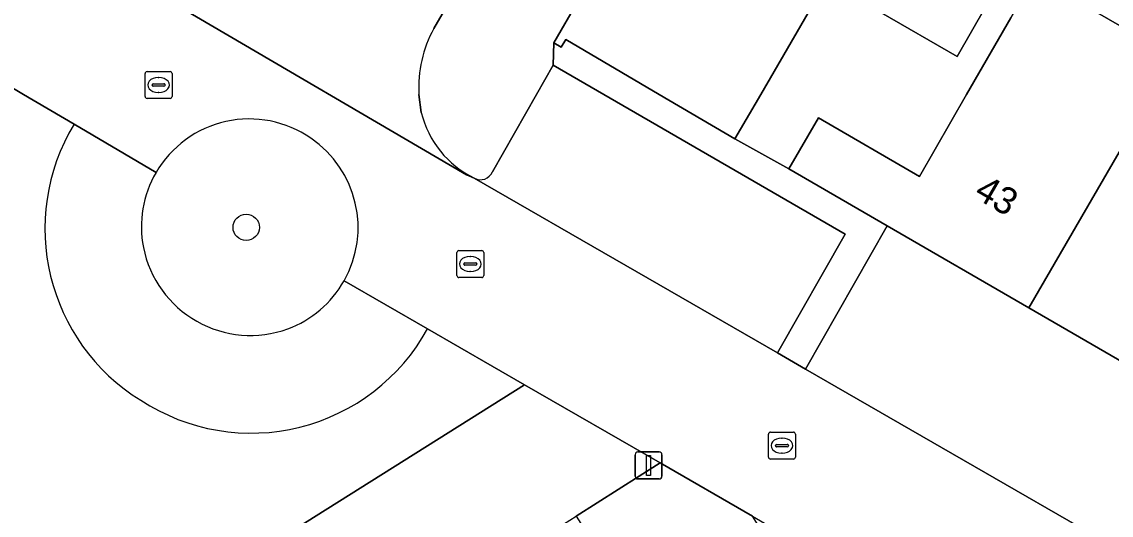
# Model space of a CAD drawing. Extents: x 160023 to 161302, y 384750 to 385707.
# Drawn here: x 160282.85 to 160323.26, y 384984.38 to 385002.69 of the extents above; entities that cross this region are included whole.
import ezdxf

# ---------------------------------------------------------------- set-up
doc = ezdxf.new("R2010")
doc.units = 0
for name, color, linetype in [('IMGEO_Boom', 7, 'Continuous'), ('IMGEO_Erf', 7, 'Continuous'), ('IMGEO_Groenvoorziening', 7, 'Continuous'), ('IMGEO_Haag', 7, 'Continuous'), ('IMGEO_Kolk', 7, 'Continuous'), ('IMGEO_Lichtmast', 7, 'Continuous'), ('IMGEO_Muur', 7, 'Continuous'), ('IMGEO_Pand', 7, 'Continuous'), ('IMGEO_Pand_nummerreeks', 7, 'Continuous'), ('IMGEO_Parkeervlak_open', 7, 'Continuous'), ('IMGEO_Rijbaan_lokaal_open', 7, 'Continuous'), ('IMGEO_Voetpad_open', 7, 'Continuous')]:
    doc.layers.add(name, color=color, linetype=linetype)

msp = doc.modelspace()

# ---------------------------------------------------------------- linework, layer by layer
at = {"layer": 'IMGEO_Boom'}
msp.add_circle((160291.176, 384995.065), 0.489, dxfattribs=at)
at = {"layer": 'IMGEO_Erf'}
for points in [[(160326.462, 385035.188), (160321.307, 385038.162), (160317.354, 385031.285), (160319.024, 385030.345), (160319.56, 385031.262), (160323.014, 385029.244), (160321.908, 385027.343), (160318.446, 385029.357), (160316.226, 385025.503), (160322.8, 385021.689), (160319.391, 385015.793), (160316.031, 385009.982), (160312.732, 385004.276), (160310.26, 385000), (160309.303, 384998.344), (160311.305, 384997.238), (160312.398, 384999.124), (160316.144, 384996.952), (160317.891, 385000), (160319.528, 385002.843), (160321.089, 385005.554), (160323.428, 385004.207), (160322.747, 385003.026), (160325.604, 385001.381)], [(160325.137, 384989.216), (160320.202, 384992.078), (160314.945, 384995.127), (160311.924, 384989.805), (160329.09, 384979.915)]]:
    msp.add_lwpolyline(points, dxfattribs=at)
msp.add_lwpolyline([(160318.609, 385003.264), (160317.539, 385001.409), (160314.716, 385003.036), (160315.785, 385004.891)], close=True, dxfattribs=at)
at = {"layer": 'IMGEO_Groenvoorziening'}
msp.add_lwpolyline([(160303.418, 384984.353), (160306.764, 384979.072), (160311.42, 384982.022), (160309.954, 384984.347), (160306.528, 384986.323)], close=True, dxfattribs=at)
for centre, radius, start, end in [((160291.291, 384995.085), 4.002, 55.2003, 149.7961), ((160291.316, 384995.056), 4.011, 330.4848, 55.7305), ((160291.288, 384995.084), 4, 149.7696, 191.0385), ((160291.338, 384995.11), 4.054, 191.2672, 289.865), ((160291.315, 384995.057), 4.012, 290.4291, 330.4795)]:
    msp.add_arc(centre, radius, start, end, dxfattribs=at)
at = {"layer": 'IMGEO_Haag'}
msp.add_lwpolyline([(160303.418, 384984.353), (160306.764, 384979.072), (160311.42, 384982.022), (160309.954, 384984.347), (160306.528, 384986.323)], close=True, dxfattribs=at)
at = {"layer": 'IMGEO_Kolk'}
for p, q in [((160287.426, 384999.92), (160287.426, 385000.772)), ((160287.501, 385000.846), (160288.353, 385000.846)), ((160287.914, 385000.626), (160287.939, 385000.626)), ((160288.427, 385000.772), (160288.427, 384999.92)), ((160287.685, 385000.34), (160287.685, 385000.352)), ((160288.123, 385000.303), (160287.725, 385000.303)), ((160287.728, 385000.389), (160288.126, 385000.389)), ((160288.169, 385000.352), (160288.169, 385000.34)), ((160288.353, 384999.846), (160287.501, 384999.846)), ((160287.937, 385000.066), (160287.912, 385000.066)), ((160298.988, 384993.278), (160298.988, 384994.13)), ((160299.063, 384994.204), (160299.915, 384994.204)), ((160299.989, 384994.13), (160299.989, 384993.278)), ((160299.247, 384993.698), (160299.247, 384993.71)), ((160299.29, 384993.747), (160299.688, 384993.747)), ((160299.476, 384993.984), (160299.501, 384993.984)), ((160299.731, 384993.71), (160299.731, 384993.698)), ((160299.685, 384993.661), (160299.287, 384993.661)), ((160299.499, 384993.424), (160299.474, 384993.424)), ((160299.915, 384993.204), (160299.063, 384993.204)), ((160310.544, 384986.54), (160310.544, 384987.392)), ((160310.619, 384987.466), (160311.471, 384987.466)), ((160311.032, 384987.246), (160311.057, 384987.246)), ((160311.545, 384987.392), (160311.545, 384986.54)), ((160310.803, 384986.96), (160310.803, 384986.972)), ((160311.241, 384986.923), (160310.843, 384986.923)), ((160310.846, 384987.009), (160311.244, 384987.009)), ((160311.287, 384986.972), (160311.287, 384986.96)), ((160311.471, 384986.466), (160310.619, 384986.466)), ((160311.055, 384986.686), (160311.03, 384986.686))]:
    msp.add_line(p, q, dxfattribs=at)
for points in [[(160287.426, 384999.92), (160287.426, 385000.772)], [(160287.501, 385000.846), (160288.353, 385000.846)], [(160288.427, 385000.772), (160288.427, 384999.92)], [(160288.353, 384999.846), (160287.501, 384999.846)], [(160298.988, 384993.278), (160298.988, 384994.13)], [(160299.063, 384994.204), (160299.915, 384994.204)], [(160299.989, 384994.13), (160299.989, 384993.278)], [(160299.915, 384993.204), (160299.063, 384993.204)], [(160310.544, 384986.54), (160310.544, 384987.392)], [(160310.619, 384987.466), (160311.471, 384987.466)], [(160311.545, 384987.392), (160311.545, 384986.54)], [(160311.471, 384986.466), (160310.619, 384986.466)]]:
    msp.add_lwpolyline(points, dxfattribs=at)
for centre, radius, start, end in [((160287.503, 385000.77), 0.0765, 91.552, 178.448), ((160287.503, 385000.77), 0.0765, 91.552, 178.448), ((160288.351, 385000.77), 0.0765, 1.552, 88.448), ((160288.351, 385000.77), 0.0765, 1.552, 88.448), ((160287.725, 385000.349), 0.0403, 85.8775, 175.7526), ((160287.722, 385000.339), 0.0366, 178.938, 274.7102), ((160288.126, 385000.346), 0.043, 264.8664, 352.4533), ((160288.13, 385000.351), 0.0386, 1.7309, 96.639), ((160287.503, 384999.922), 0.0765, 181.552, 268.448), ((160287.503, 384999.922), 0.0765, 181.552, 268.448), ((160288.351, 384999.922), 0.0765, 271.552, 358.448), ((160288.351, 384999.922), 0.0765, 271.552, 358.448), ((160299.065, 384994.128), 0.0765, 91.552, 178.448), ((160299.065, 384994.128), 0.0765, 91.552, 178.448), ((160299.913, 384994.128), 0.0765, 1.552, 88.448), ((160299.913, 384994.128), 0.0765, 1.552, 88.448), ((160299.287, 384993.707), 0.0403, 85.8775, 175.7526), ((160299.284, 384993.697), 0.0366, 178.938, 274.7102), ((160299.688, 384993.704), 0.043, 264.8664, 352.4533), ((160299.692, 384993.709), 0.0386, 1.7309, 96.639), ((160299.065, 384993.28), 0.0765, 181.552, 268.448), ((160299.065, 384993.28), 0.0765, 181.552, 268.448), ((160299.913, 384993.28), 0.0765, 271.552, 358.448), ((160299.913, 384993.28), 0.0765, 271.552, 358.448), ((160310.621, 384987.39), 0.0765, 91.552, 178.448), ((160310.621, 384987.39), 0.0765, 91.552, 178.448), ((160311.469, 384987.39), 0.0765, 1.552, 88.448), ((160311.469, 384987.39), 0.0765, 1.552, 88.448), ((160310.843, 384986.969), 0.0403, 85.8775, 175.7526), ((160310.84, 384986.959), 0.0366, 178.938, 274.7102), ((160311.244, 384986.966), 0.043, 264.8664, 352.4533), ((160311.248, 384986.971), 0.0386, 1.7309, 96.639), ((160310.621, 384986.542), 0.0765, 181.552, 268.448), ((160310.621, 384986.542), 0.0765, 181.552, 268.448), ((160311.469, 384986.542), 0.0765, 271.552, 358.448), ((160311.469, 384986.542), 0.0765, 271.552, 358.448)]:
    msp.add_arc(centre, radius, start, end, dxfattribs=at)
for centre, major_axis, ratio, start_param, end_param in [((160287.913, 385000.346), (-0.387, 0.002), 0.722429, 4.712389, 7.853982), ((160287.938, 385000.346), (-0.39, 0.002), 0.717154, 1.570796, 4.712389), ((160299.475, 384993.704), (-0.387, 0.002), 0.722429, 4.712389, 7.853982), ((160299.5, 384993.704), (-0.39, 0.002), 0.717154, 1.570796, 4.712389), ((160311.031, 384986.966), (-0.387, 0.002), 0.722429, 4.712389, 7.853982), ((160311.056, 384986.966), (-0.39, 0.002), 0.717154, 1.570796, 4.712389)]:
    msp.add_ellipse(centre, major_axis=major_axis, ratio=ratio, start_param=start_param, end_param=end_param, dxfattribs=at)
at = {"layer": 'IMGEO_Lichtmast'}
for p, q in [((160305.603, 384985.83), (160305.603, 384986.63)), ((160305.603, 384986.63), (160305.603, 384985.83)), ((160305.703, 384986.73), (160306.493, 384986.73)), ((160306.493, 384986.73), (160305.703, 384986.73)), ((160306.593, 384986.63), (160306.593, 384985.83)), ((160306.593, 384985.83), (160306.593, 384986.63)), ((160306.493, 384985.73), (160305.703, 384985.73)), ((160305.703, 384985.73), (160306.493, 384985.73))]:
    msp.add_line(p, q, dxfattribs=at)
msp.add_lwpolyline([(160306.023, 384986.605), (160306.173, 384986.605), (160306.173, 384985.855), (160306.023, 384985.855), (160306.023, 384986.605)], dxfattribs=at)
for centre, start, end in [((160305.703, 384986.63), 90, 180), ((160305.703, 384986.63), 90, 180), ((160306.493, 384986.63), 0, 90), ((160306.493, 384986.63), 360, 90), ((160305.703, 384985.83), 180, 270), ((160305.703, 384985.83), 180, 270), ((160306.493, 384985.83), 270, 0), ((160306.493, 384985.83), 270, 0)]:
    msp.add_arc(centre, 0.1, start, end, dxfattribs=at)
at = {"layer": 'IMGEO_Muur'}
msp.add_lwpolyline([(160309.303, 384998.344), (160311.305, 384997.238)], dxfattribs=at)
at = {"layer": 'IMGEO_Pand'}
for points in [[(160302.587, 385001.917), (160302.863, 385001.754), (160303.031, 385002.04), (160306.493, 385000), (160309.303, 384998.344), (160310.26, 385000), (160312.732, 385004.276), (160306.193, 385008.153)], [(160324.717, 384999.853), (160325.604, 385001.381), (160322.747, 385003.026), (160323.428, 385004.207), (160321.089, 385005.554), (160319.528, 385002.843), (160317.891, 385000), (160316.144, 384996.952), (160312.398, 384999.124), (160311.305, 384997.238), (160314.945, 384995.127), (160320.202, 384992.078)], [(160314.716, 385003.036), (160317.539, 385001.409), (160318.609, 385003.264), (160315.785, 385004.891)], [(160329.651, 384997.009), (160331.266, 384999.797), (160326.335, 385002.64), (160325.604, 385001.381), (160324.717, 384999.853), (160320.202, 384992.078), (160325.137, 384989.216)]]:
    msp.add_lwpolyline(points, close=True, dxfattribs=at)
at = {"layer": 'IMGEO_Parkeervlak_open'}
msp.add_lwpolyline([(160299.637, 384996.89), (160310.878, 384990.412), (160313.384, 384994.807), (160304.438, 385000), (160302.566, 385001.087), (160301.947, 385000), (160300.306, 384997.12)], dxfattribs=at)
msp.add_lwpolyline([(160306.528, 384986.323), (160301.494, 384989.225), (160284.846, 384978.742), (160287.618, 384974.398), (160300.363, 384982.417), (160303.418, 384984.353)], close=True, dxfattribs=at)
msp.add_arc((160299.867, 384997.309), 0.478, 241.2723, 336.6733, dxfattribs=at)
at = {"layer": 'IMGEO_Rijbaan_lokaal_open'}
for points in [[(160298.133, 385002.441), (160299.328, 385004.495), (160301.364, 385007.975), (160310.622, 385023.967), (160312.148, 385026.623), (160312.692, 385027.574), (160315.342, 385032.116), (160319.833, 385039.862), (160338.122, 385071.424)], [(160288.826, 385003.17), (160277.546, 385009.762), (160276.493, 385010.365), (160261.202, 385019.264), (160260.583, 385016.811), (160257.45, 385014.824), (160280.916, 385001.181), (160282.916, 385000), (160284.795, 384998.891), (160287.832, 384997.098)], [(160288.826, 385003.17), (160299.342, 384997.013), (160299.637, 384996.89)], [(160294.807, 384993.08), (160297.902, 384991.296), (160301.494, 384989.225), (160306.528, 384986.323), (160309.954, 384984.347), (160310.546, 384984.006), (160311.625, 384983.376), (160316.844, 384975.01), (160323.19, 384978.952), (160325.802, 384974.741), (160331.674, 384978.392), (160329.942, 384979.419), (160329.09, 384979.915), (160311.924, 384989.805), (160310.878, 384990.412), (160299.637, 384996.89), (160299.342, 384997.013), (160288.826, 385003.17)], [(160284.795, 384998.891), (160282.916, 385000), (160280.916, 385001.181), (160280.879, 385000), (160280.762, 384996.321), (160280.224, 384981.464), (160284.846, 384978.742), (160301.494, 384989.225), (160297.902, 384991.296)], [(160297.668, 384999.33), (160297.581, 385000)], [(160287.832, 384997.098), (160284.795, 384998.891)], [(160297.902, 384991.296), (160294.807, 384993.08)]]:
    msp.add_lwpolyline(points, dxfattribs=at)
for centre, radius, start, end in [((160302.128, 385000.255), 4.554, 151.3098, 183.2055), ((160301.247, 385000.203), 3.684, 193.7161, 244.0887), ((160291.291, 384995.085), 4.002, 55.2003, 149.7961), ((160291.186, 384995.016), 7.474, 148.7714, 238.4467), ((160291.186, 384995.016), 7.474, 148.7714, 238.4467), ((160291.316, 384995.056), 4.011, 330.4848, 55.7305), ((160291.288, 384995.084), 4, 149.7696, 191.0385), ((160291.338, 384995.11), 4.054, 191.2672, 289.865), ((160291.315, 384995.057), 4.012, 290.4291, 330.4795), ((160291.361, 384994.895), 7.465, 236.8131, 331.1807), ((160291.361, 384994.895), 7.465, 236.8131, 331.1807)]:
    msp.add_arc(centre, radius, start, end, dxfattribs=at)
at = {"layer": 'IMGEO_Voetpad_open'}
for points in [[(160300.306, 384997.12), (160301.947, 385000), (160302.566, 385001.087), (160302.587, 385001.917), (160306.193, 385008.153), (160309.494, 385013.861), (160312.785, 385019.552), (160316.226, 385025.503), (160318.446, 385029.357), (160319.024, 385030.345), (160317.354, 385031.285), (160321.307, 385038.162), (160325.384, 385045.224), (160325.286, 385045.271)], [(160299.328, 385004.495), (160298.133, 385002.441)], [(160297.581, 385000), (160297.668, 384999.33)]]:
    msp.add_lwpolyline(points, dxfattribs=at)
msp.add_lwpolyline([(160306.493, 385000), (160303.031, 385002.04), (160302.863, 385001.754), (160302.587, 385001.917), (160302.566, 385001.087), (160304.438, 385000), (160313.384, 384994.807), (160310.878, 384990.412), (160311.924, 384989.805), (160314.945, 384995.127), (160311.305, 384997.238), (160309.303, 384998.344)], close=True, dxfattribs=at)
for centre, radius, start, end in [((160302.128, 385000.255), 4.554, 151.3098, 183.2055), ((160301.247, 385000.203), 3.684, 193.7161, 244.0887), ((160299.867, 384997.309), 0.478, 241.2723, 336.6733)]:
    msp.add_arc(centre, radius, start, end, dxfattribs=at)

# ---------------------------------------------------------------- texts
at = {"layer": 'IMGEO_Pand_nummerreeks'}
msp.add_text('43', height=1, rotation=329.8968, dxfattribs=at).set_placement((160318.123, 384996.197))

doc.saveas('drawing.dxf')
